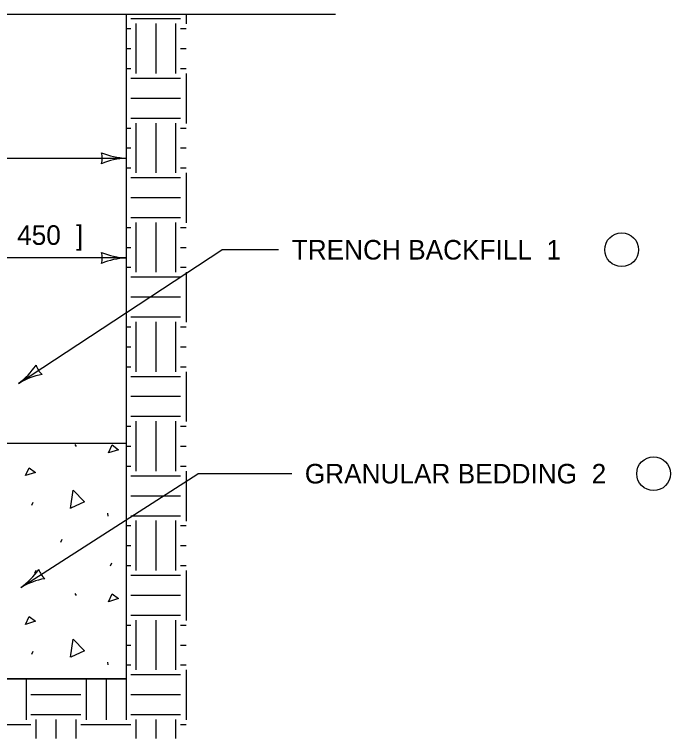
# Model space of a CAD drawing. Extents: x 49977.1 to 50021, y 49987.6 to 50011.4.
# Drawn here: x 49982.305 to 49985.958, y 49999.941 to 50003.976 of the extents above; entities that cross this region are included whole.
import ezdxf

# ---------------------------------------------------------------- set-up
doc = ezdxf.new("R2010")
doc.units = 0
for name, color, linetype in [('Level 1', 7, 'Continuous'), ('Level 2', 7, 'Continuous'), ('Level 3', 7, 'Continuous')]:
    doc.layers.add(name, color=color, linetype=linetype)

msp = doc.modelspace()

# ---------------------------------------------------------------- linework, layer by layer
at = {"layer": 'Level 1'}
for p, q in [((49984.0926, 50003.9758), (49977.1347, 50003.9758)), ((49982.9277, 50003.9758), (49982.9277, 50000.2744)), ((49983.2603, 50003.9758), (49983.2603, 50003.9231)), ((49982.9522, 50003.9528), (49983.2304, 50003.9528)), ((49982.98, 50003.925), (49982.98, 50003.6471)), ((49983.0913, 50003.925), (49983.0913, 50003.6471)), ((49983.2026, 50003.925), (49983.2026, 50003.6471)), ((49982.9277, 50003.8972), (49982.9522, 50003.8972)), ((49983.2304, 50003.8972), (49983.2613, 50003.8972)), ((49982.9277, 50003.786), (49982.9522, 50003.786)), ((49983.2304, 50003.786), (49983.2613, 50003.786)), ((49982.9277, 50003.6749), (49982.9522, 50003.6749)), ((49983.2304, 50003.6749), (49983.2613, 50003.6749)), ((49983.2603, 50003.6471), (49983.2603, 50003.3691)), ((49982.9522, 50003.6212), (49983.2304, 50003.6212)), ((49982.9522, 50003.51), (49983.2304, 50003.51)), ((49982.9522, 50003.3988), (49983.2304, 50003.3988)), ((49982.98, 50003.371), (49982.98, 50003.0931)), ((49983.0913, 50003.371), (49983.0913, 50003.0931)), ((49983.2026, 50003.371), (49983.2026, 50003.0931)), ((49982.9277, 50003.3432), (49982.9522, 50003.3432)), ((49983.2304, 50003.3432), (49983.2613, 50003.3432)), ((49982.9277, 50003.2321), (49982.9522, 50003.2321)), ((49983.2304, 50003.2321), (49983.2613, 50003.2321)), ((49982.9277, 50003.1209), (49982.9522, 50003.1209)), ((49983.2304, 50003.1209), (49983.2613, 50003.1209)), ((49983.2603, 50003.0931), (49983.2603, 50002.8151)), ((49982.9522, 50003.0672), (49983.2304, 50003.0672)), ((49982.9522, 50002.956), (49983.2304, 50002.956)), ((49982.9522, 50002.8448), (49983.2304, 50002.8448)), ((49982.98, 50002.817), (49982.98, 50002.5391)), ((49983.0913, 50002.817), (49983.0913, 50002.5391)), ((49983.2026, 50002.817), (49983.2026, 50002.5391)), ((49982.9277, 50002.7892), (49982.9522, 50002.7892)), ((49983.2304, 50002.7892), (49983.2613, 50002.7892)), ((49982.9277, 50002.6781), (49982.9522, 50002.6781)), ((49983.2304, 50002.6781), (49983.2613, 50002.6781)), ((49982.9277, 50002.5669), (49982.9522, 50002.5669)), ((49983.2304, 50002.5669), (49983.2613, 50002.5669)), ((49982.9522, 50002.5132), (49983.2304, 50002.5132)), ((49983.2603, 50002.5391), (49983.2603, 50002.2611)), ((49982.9522, 50002.402), (49983.2304, 50002.402)), ((49982.9522, 50002.2908), (49983.2304, 50002.2908)), ((49982.9277, 50002.2352), (49982.9522, 50002.2352)), ((49982.98, 50002.263), (49982.98, 50001.9851)), ((49983.0913, 50002.263), (49983.0913, 50001.9851)), ((49983.2026, 50002.263), (49983.2026, 50001.9851)), ((49983.2304, 50002.2352), (49983.2613, 50002.2352)), ((49982.9277, 50002.1241), (49982.9522, 50002.1241)), ((49983.2304, 50002.1241), (49983.2613, 50002.1241)), ((49982.9277, 50002.0129), (49982.9522, 50002.0129)), ((49983.2304, 50002.0129), (49983.2613, 50002.0129)), ((49983.2603, 50001.9851), (49983.2603, 50001.7071)), ((49982.9522, 50001.9592), (49983.2304, 50001.9592)), ((49982.9522, 50001.848), (49983.2304, 50001.848)), ((49982.9522, 50001.7369), (49983.2304, 50001.7369)), ((49982.98, 50001.7091), (49982.98, 50001.4311)), ((49983.0913, 50001.7091), (49983.0913, 50001.4311)), ((49983.2026, 50001.7091), (49983.2026, 50001.4311)), ((49982.9277, 50001.6813), (49982.9522, 50001.6813)), ((49983.2304, 50001.6813), (49983.2613, 50001.6813)), ((49981.4269, 50001.5869), (49982.9277, 50001.5869)), ((49982.9277, 50001.5869), (49982.9277, 50000.2744)), ((49982.6414, 50001.5791), (49982.6485, 50001.5684)), ((49982.9277, 50001.5701), (49982.9522, 50001.5701)), ((49983.2304, 50001.5701), (49983.2613, 50001.5701)), ((49982.9277, 50001.4589), (49982.9522, 50001.4589)), ((49983.2304, 50001.4589), (49983.2613, 50001.4589)), ((49983.2603, 50001.4311), (49983.2603, 50001.1531)), ((49982.9522, 50001.4052), (49983.2304, 50001.4052)), ((49982.9522, 50001.2941), (49983.2304, 50001.2941)), ((49982.4014, 50001.2416), (49982.4085, 50001.2576)), ((49982.824, 50001.197), (49982.8258, 50001.181)), ((49982.9522, 50001.1829), (49983.2304, 50001.1829)), ((49982.98, 50001.1551), (49982.98, 50000.8771)), ((49983.0913, 50001.1551), (49983.0913, 50000.8771)), ((49983.2026, 50001.1551), (49983.2026, 50000.8771)), ((49982.9277, 50001.1273), (49982.9522, 50001.1273)), ((49983.2304, 50001.1273), (49983.2613, 50001.1273)), ((49982.5631, 50001.0356), (49982.5703, 50001.0516)), ((49982.9277, 50001.0161), (49982.9522, 50001.0161)), ((49983.2304, 50001.0161), (49983.2613, 50001.0161)), ((49982.8405, 50000.904), (49982.8476, 50000.92)), ((49982.9277, 50000.9049), (49982.9522, 50000.9049)), ((49983.2304, 50000.9049), (49983.2613, 50000.9049)), ((49982.4191, 50000.8631), (49982.4263, 50000.8791)), ((49983.2603, 50000.8771), (49983.2603, 50000.5991)), ((49982.9522, 50000.8512), (49983.2304, 50000.8512)), ((49982.6414, 50000.7495), (49982.6485, 50000.7388)), ((49982.9522, 50000.7401), (49983.2304, 50000.7401)), ((49982.9522, 50000.6289), (49983.2304, 50000.6289)), ((49982.9277, 50000.5733), (49982.9522, 50000.5733)), ((49982.98, 50000.6011), (49982.98, 50000.3231)), ((49983.0913, 50000.6011), (49983.0913, 50000.3231)), ((49983.2026, 50000.6011), (49983.2026, 50000.3231)), ((49983.2304, 50000.5733), (49983.2613, 50000.5733)), ((49982.9277, 50000.4621), (49982.9522, 50000.4621)), ((49983.2304, 50000.4621), (49983.2613, 50000.4621)), ((49982.4014, 50000.412), (49982.4085, 50000.428)), ((49982.824, 50000.3674), (49982.8258, 50000.3514)), ((49982.9277, 50000.3509), (49982.9522, 50000.3509)), ((49983.2304, 50000.3509), (49983.2613, 50000.3509)), ((49982.9522, 50000.2972), (49983.2304, 50000.2972)), ((49983.2603, 50000.3231), (49983.2603, 50000.0451)), ((49982.9277, 50000.2744), (49978.2996, 50000.2744)), ((49978.2996, 50000.2744), (49982.9277, 50000.2744)), ((49982.37, 50000.2744), (49982.37, 50000.0451)), ((49982.7039, 50000.2744), (49982.7039, 50000.0451)), ((49982.8152, 50000.2744), (49982.8152, 50000.0451)), ((49982.9265, 50000.2744), (49982.9265, 50000.0451)), ((49982.3958, 50000.1861), (49982.674, 50000.1861)), ((49982.9522, 50000.1861), (49983.2304, 50000.1861)), ((49982.3958, 50000.0749), (49982.674, 50000.0749)), ((49982.9522, 50000.0749), (49983.2304, 50000.0749)), ((49982.1175, 50000.0193), (49982.3958, 50000.0193)), ((49982.4236, 50000.0471), (49982.4236, 49999.9411)), ((49982.5349, 50000.0471), (49982.5349, 49999.9411)), ((49982.6462, 50000.0471), (49982.6462, 49999.9411)), ((49982.674, 50000.0193), (49982.9522, 50000.0193)), ((49982.98, 50000.0471), (49982.98, 49999.9411)), ((49983.0913, 50000.0471), (49983.0913, 49999.9411)), ((49983.2026, 50000.0471), (49983.2026, 49999.9411)), ((49983.2304, 50000.0193), (49983.2613, 50000.0193))]:
    msp.add_line(p, q, dxfattribs=at)
for points in [[(49982.828, 50001.5329), (49982.8493, 50001.5773), (49982.8849, 50001.5507), (49982.828, 50001.5329)], [(49982.3662, 50001.4059), (49982.3875, 50001.4504), (49982.4231, 50001.4237), (49982.3662, 50001.4059)], [(49982.6176, 50001.2233), (49982.6317, 50001.3248), (49982.6954, 50001.2591), (49982.6193, 50001.2239)], [(49982.828, 50000.7033), (49982.8493, 50000.7477), (49982.8849, 50000.721), (49982.828, 50000.7033)], [(49982.3662, 50000.5763), (49982.3875, 50000.6207), (49982.4231, 50000.5941), (49982.3662, 50000.5763)], [(49982.6176, 50000.3936), (49982.6317, 50000.4951), (49982.6954, 50000.4295), (49982.6193, 50000.3942)]]:
    msp.add_lwpolyline(points, dxfattribs=at)
at = {"layer": 'Level 2'}
for centre in [(49985.6857, 50002.6647), (49985.8634, 50001.4169)]:
    msp.add_ellipse(centre, major_axis=(-0.0942, 0), ratio=0.999067, dxfattribs=at)
at = {"layer": 'Level 3'}
for p, q in [((49978.2996, 50003.1749), (49982.9277, 50003.1749)), ((49982.3269, 50001.9199), (49983.46, 50002.6647)), ((49983.7759, 50002.6647), (49983.46, 50002.6647)), ((49982.9277, 50002.6192), (49981.4269, 50002.6192)), ((49982.3409, 50000.7826), (49983.3255, 50001.4169)), ((49983.8488, 50001.4169), (49983.3255, 50001.4169))]:
    msp.add_line(p, q, dxfattribs=at)
for centre, major_axis, start_param, end_param in [((49982.9443, 50003.5788), (0.4046, 0), 4.318922, 4.671191), ((49982.6943, 50003.1749), (0.0997, 0), 5.971449, 6.594922), ((49982.9486, 50002.7518), (-0.424, 0), 4.761735, 5.097708), ((49982.9443, 50003.0231), (0.4046, 0), 4.318922, 4.671191), ((49982.6943, 50002.6192), (0.0997, 0), 5.971449, 6.594922), ((49982.9486, 50002.1961), (-0.424, 0), 4.761735, 5.097708), ((49982.0767, 50002.2618), (0.424, 0), 5.343722, 5.679695), ((49982.5219, 50002.048), (-0.0997, 0), 0.270251, 0.893723), ((49982.5352, 50001.5733), (-0.4046, 0), 4.900909, 5.253178), ((49982.0939, 50001.1269), (0.424, 0), 5.334452, 5.670425), ((49982.537, 50000.9089), (-0.0997, 0), 0.260981, 0.884454), ((49982.546, 50000.4341), (-0.4046, 0), 4.891639, 5.243908)]:
    msp.add_ellipse(centre, major_axis=major_axis, ratio=0.999067, start_param=start_param, end_param=end_param, dxfattribs=at)

# ---------------------------------------------------------------- texts
at = {"layer": 'Level 2'}
for s, height, p in [('450', 0.10909, (49982.32, 50002.692)), (']', 0.1091, (49982.6476, 50002.692)), ('TRENCH BACKFILL  1', 0.109091, (49983.8488, 50002.6102)), ('GRANULAR BEDDING  2', 0.109091, (49983.9216, 50001.3623))]:
    msp.add_text(s, height=height, dxfattribs=at).set_placement(p)

doc.saveas('drawing.dxf')
